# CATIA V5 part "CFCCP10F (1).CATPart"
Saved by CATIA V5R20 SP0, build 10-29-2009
Part number: CFCCP10F (1)
Revision: TUTTO
Definition: NON CONOSCIUTO
Nomenclature: CFCCP10F (1)
Source: Unknown
Bounding box of the stored display mesh (mm): x -50 to 50, y -29 to 29, z 0 to 10.5
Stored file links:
  C:\Users\Utente\Desktop\IO LAVORO\3D X SITO CF\X 3D SITO CF 27-09-2020\CFCCP\CFCCP10F\CFCCP10F (1).CATPart
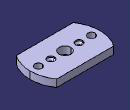
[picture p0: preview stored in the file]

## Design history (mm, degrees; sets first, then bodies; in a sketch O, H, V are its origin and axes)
Body1 "Foro Ø5.5 (5.5)-1" (main body)
  Solid1: solid without history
